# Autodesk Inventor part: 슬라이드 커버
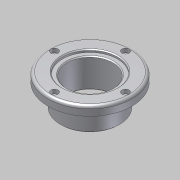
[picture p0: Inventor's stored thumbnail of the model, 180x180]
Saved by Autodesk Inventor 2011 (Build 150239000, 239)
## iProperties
Created: 2013-06
Part Number: 슬라이드 커버
Document SubType Name: Modeling
Designer: SeoGD™[esajin.kr]
Density: 1 g/cm^3
Author: SeoGD™[esajin.kr]
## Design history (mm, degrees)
sketch "스케치1"
  geometry: C1 r 46 at (0, -39.25) reference; C2 r 32.5 at (0, -39.25) reference; 1 further point
  node "참조1"
  node "참조2"
extrude "돌출1" new body sketch "스케치1" distance "d0" = 10; taper "d1" = 0 deg
extrude "돌출2" join sketch "스케치1" distance "d2" = 25; taper "d3" = 0 deg
hole "구멍1" diameter "d6" = 50; stored, may be unused: countersink angle "d10" = 90 deg, drill point angle "d12" = 118 deg; dims "d4" = 10, "d5" = 10, "d7" = 6, "d8" = 4, "d9" = 2, "d11" = 8
sketch "스케치2"
  geometry: C1 r 46 at (0, 0) reference; C2 r 1.621 at (0, 39) reference; C3 r 1.621 at (39, 0) reference; C4 r 1.621 at (0, -39) reference; C5 r 1.621 at (-39, 0) reference; C6 r 33.5 at (0, 0) reference; 1 further point
hole "구멍2" sketch "스케치2" at (0, 39) diameter "d13" = 4.5; stored, may be unused: countersink angle "d17" = 90 deg, drill point angle "d19" = 118 deg; dims "d14" = 6, "d15" = 8, "d16" = 4.4, "d18" = 8
fillet "모깎기1" dims "d23" = 3
chamfer "모따기1" distance "d24" = 1; stored, may be unused: second distance "d25" = 2, angle "d26" = 45 deg
sketch "스케치3"
  geometry: C1 r 25 at (39, 0) reference; C2 r 30 at (39, 0); 1 further point
  constraints: 1 centre point, 1 coincident
  dimensions: "d27" = 60 diameter of C2
extrude "돌출3" cut sketch "스케치3" distance "d28" = 3; taper "d29" = 0 deg
chamfer "모따기2" distance "d30" = 1; stored, may be unused: second distance "d31" = 2, angle "d32" = 45 deg
node "솔리드1"
pattern_circular "원형 패턴1" dims angle "d21" = 360 deg
node "참조3"
